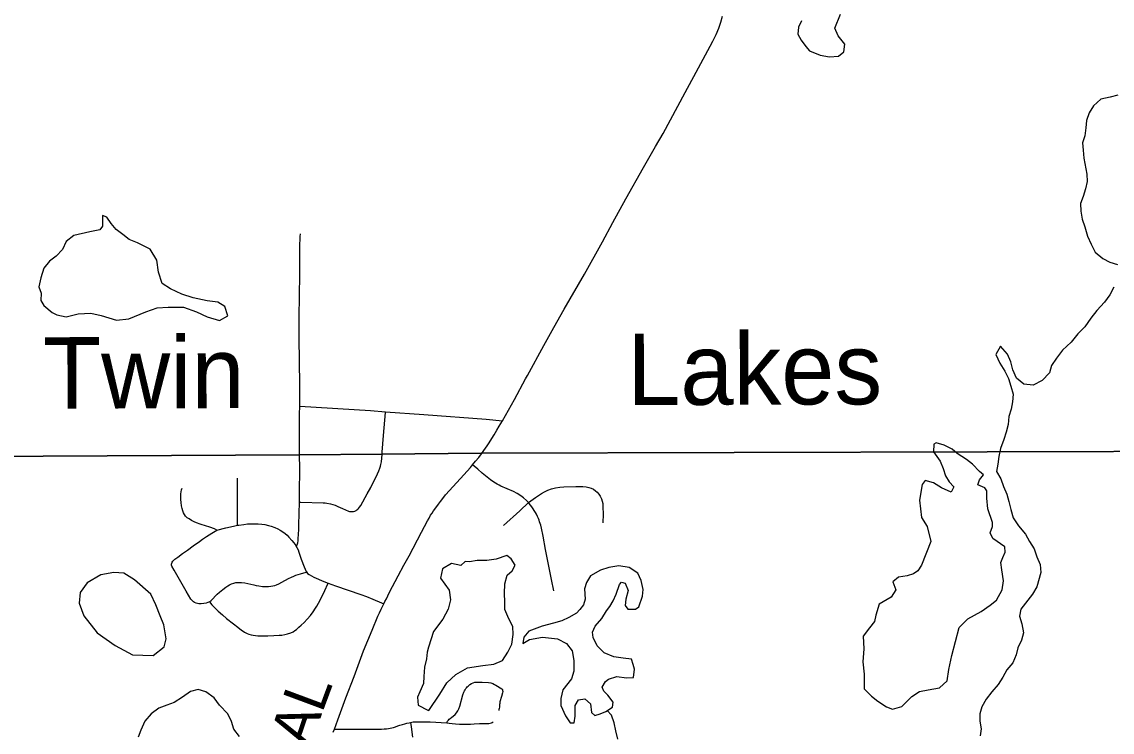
# Model space of a CAD drawing. Extents: x 0 to 34, y 0 to 22.
# Drawn here: x 3.103 to 4.548, y 17.124 to 18.065 of the extents above; entities that cross this region are included whole.
import ezdxf

# ---------------------------------------------------------------- set-up
doc = ezdxf.new("R2010")
doc.units = 0
for name, color, linetype in [('GM_X_City_Street', 7, 'Continuous'), ('GM_X_Corporation', 7, 'Continuous'), ('GM_X_County_Road', 7, 'Continuous'), ('GM_X_County_Road_Text', 7, 'Continuous'), ('GM_X_Major_Lake', 7, 'Continuous'), ('GM_X_Minor_Lake', 7, 'Continuous'), ('GM_X_Minor_Lake_Text', 7, 'Continuous'), ('GM_X_Minor_River', 7, 'Continuous'), ('GM_X_Township_Road', 7, 'Continuous')]:
    doc.layers.add(name, color=color, linetype=linetype)

msp = doc.modelspace()

# ---------------------------------------------------------------- linework, layer by layer
at = {"layer": 'GM_X_City_Street'}
for points in [[(3.4712, 17.556), (3.4711, 17.5721), (3.4711, 17.5882), (3.4709, 17.6117), (3.4705, 17.6502), (3.4703, 17.6723), (3.4707, 17.7039), (3.4712, 17.7287), (3.4712, 17.7673), (3.4714, 17.7711), (3.4716, 17.7764), (3.4719, 17.7806), (3.4724, 17.7843)], [(3.4712, 17.556), (3.5651, 17.5501), (3.5849, 17.5486), (3.6358, 17.5448), (3.7183, 17.5386), (3.7401, 17.5366)]]:
    msp.add_lwpolyline(points, dxfattribs=at)
at = {"layer": 'GM_X_Corporation'}
for points in [[(2.1, 20.9), (2.1, 17.4875), (2.1449, 17.4882), (2.5812, 17.4925), (2.6352, 17.4929), (3.0456, 17.4894), (3.4708, 17.4915), (3.5801, 17.4924), (3.7119, 17.4934), (4.718, 17.4962)], [(4.718, 17.4962), (3.7119, 17.4934), (3.5801, 17.4924), (3.4708, 17.4915), (3.0456, 17.4894), (2.6352, 17.4929), (2.5812, 17.4925), (2.1449, 17.4882), (2.1, 17.4875), (2.1, 14.1), (5.0398, 14.1)], [(3.0456, 17.4894), (3.4708, 17.4915), (3.5801, 17.4924), (3.7119, 17.4934), (4.718, 17.4962)]]:
    msp.add_lwpolyline(points, dxfattribs=at)
at = {"layer": 'GM_X_County_Road'}
for points in [[(3.7706, 17.592), (3.773, 17.5964), (3.7947, 17.6362), (3.8081, 17.66), (3.8218, 17.6844), (3.8485, 17.7307), (3.8724, 17.7735), (3.8861, 17.7992), (3.9036, 17.8307), (3.927, 17.8724), (3.9427, 17.9), (3.9528, 17.9171), (3.9629, 17.9356), (3.9822, 17.9717), (3.9967, 17.9985), (4.0152, 18.033), (4.0189, 18.0396), (4.0232, 18.0487), (4.0266, 18.0568), (4.0294, 18.0647), (4.0318, 18.0727)], [(3.7401, 17.5366), (3.7557, 17.5648), (3.7706, 17.592)], [(3.7121, 17.4928), (3.7152, 17.4971), (3.7176, 17.5003), (3.7198, 17.5034), (3.7224, 17.5074), (3.726, 17.513), (3.7289, 17.5179), (3.7325, 17.5239), (3.7356, 17.5294), (3.7401, 17.5366)], [(3.7003, 17.4781), (3.7044, 17.483), (3.7084, 17.4878), (3.7121, 17.4928)], [(3.5825, 17.2937), (3.5841, 17.297), (3.586, 17.3007), (3.588, 17.3046), (3.5904, 17.3093), (3.6016, 17.3308), (3.6093, 17.345), (3.6161, 17.3575), (3.6328, 17.3887), (3.6405, 17.4037), (3.6426, 17.4073), (3.6447, 17.4113), (3.6466, 17.4142), (3.6484, 17.4171), (3.6515, 17.4212), (3.655, 17.4262), (3.6577, 17.4295), (3.661, 17.4337), (3.6646, 17.4382), (3.6845, 17.4601), (3.6976, 17.4748), (3.7003, 17.4781)], [(3.5172, 17.1279), (3.5216, 17.1401), (3.5324, 17.1693), (3.5434, 17.1977), (3.5559, 17.2315), (3.567, 17.2591), (3.5747, 17.2774), (3.5768, 17.2818), (3.5792, 17.2869), (3.5818, 17.2923), (3.5825, 17.2937)], [(3.5157, 17.1237), (3.5172, 17.1279)]]:
    msp.add_lwpolyline(points, dxfattribs=at)
at = {"layer": 'GM_X_Major_Lake'}
for points in [[(4.5556, 17.9683), (4.5455, 17.9655), (4.5334, 17.9628), (4.5236, 17.954), (4.5176, 17.9445), (4.5143, 17.9346), (4.5132, 17.9247), (4.5122, 17.9144), (4.5088, 17.9049), (4.5097, 17.8951), (4.5105, 17.8845), (4.5145, 17.8633), (4.5149, 17.8538), (4.5131, 17.8439), (4.5098, 17.834), (4.5064, 17.8245), (4.5065, 17.8143), (4.5085, 17.8037), (4.512, 17.7935), (4.5155, 17.7814), (4.5205, 17.7708), (4.5259, 17.7602), (4.5358, 17.7516), (4.5453, 17.7467), (4.5551, 17.7437)], [(4.5504, 17.7134), (4.5452, 17.7035), (4.5381, 17.6939), (4.528, 17.6828), (4.5201, 17.6725), (4.5119, 17.6611), (4.5029, 17.6516), (4.4939, 17.6409), (4.4822, 17.6302), (4.4743, 17.6195), (4.468, 17.6099), (4.465, 17.6001), (4.4553, 17.5901), (4.4436, 17.5836), (4.4311, 17.585), (4.4216, 17.5929), (4.4166, 17.6042), (4.4138, 17.6148), (4.4096, 17.6247), (4.4, 17.6352), (4.3941, 17.6245), (4.3991, 17.6128), (4.406, 17.6023), (4.4106, 17.5924), (4.4137, 17.5826), (4.4168, 17.5716), (4.4161, 17.5618), (4.4143, 17.5519), (4.4114, 17.542), (4.4103, 17.5318), (4.4077, 17.5215), (4.4044, 17.5116), (4.4003, 17.4998), (4.3978, 17.4892), (4.3967, 17.4789), (4.3949, 17.4694), (4.4007, 17.4596), (4.4041, 17.4494), (4.4084, 17.4392), (4.4111, 17.4294), (4.4138, 17.4188), (4.417, 17.4078), (4.4242, 17.3972), (4.4334, 17.3863), (4.4388, 17.3765), (4.4449, 17.3667), (4.4484, 17.3561), (4.4526, 17.3459), (4.4535, 17.3356), (4.4483, 17.3166), (4.4427, 17.3067), (4.427, 17.2869), (4.4255, 17.2774), (4.4283, 17.2672), (4.4306, 17.2555), (4.4281, 17.2456), (4.4232, 17.2357), (4.421, 17.2262), (4.4166, 17.2159), (4.4087, 17.2064), (4.4035, 17.1968), (4.3971, 17.1869), (4.3885, 17.1774), (4.3814, 17.1675), (4.3754, 17.1576), (4.3728, 17.1481), (4.3729, 17.1386), (4.3745, 17.1284), (4.3734, 17.1189)]]:
    msp.add_lwpolyline(points, dxfattribs=at)
at = {"layer": 'GM_X_Minor_Lake'}
for p, q in [((4.1358, 18.0412), (4.1423, 18.0326)), ((3.1282, 17.7057), (3.1279, 17.6959)), ((4.3078, 17.3766), (4.2956, 17.345)), ((3.2736, 17.3068), (3.2523, 17.3256)), ((3.8485, 17.3139), (3.8497, 17.3002)), ((3.6487, 17.2573), (3.6421, 17.2364))]:
    msp.add_line(p, q, dxfattribs=at)
for points in [[(4.1423, 18.0326), (4.1472, 18.0269), (4.1613, 18.0209), (4.1734, 18.0188), (4.1855, 18.0196), (4.1923, 18.0257), (4.1937, 18.0356), (4.1849, 18.0469), (4.1807, 18.0571), (4.1881, 18.0754)], [(4.1363, 18.0666), (4.1322, 18.0583), (4.1315, 18.0488), (4.1358, 18.0412)], [(3.1279, 17.6959), (3.1318, 17.6891), (3.1428, 17.68), (3.1493, 17.6771), (3.1614, 17.6745), (3.1776, 17.6784), (3.1943, 17.6793), (3.2079, 17.676), (3.2284, 17.6701), (3.2447, 17.6717), (3.2673, 17.681), (3.2824, 17.6861), (3.2968, 17.6873), (3.3172, 17.6871), (3.3343, 17.6808), (3.3484, 17.6741), (3.3647, 17.6693), (3.376, 17.6758), (3.3721, 17.6879), (3.3626, 17.6939), (3.3486, 17.6953), (3.33, 17.6997), (3.3148, 17.7045), (3.3, 17.7112), (3.289, 17.7183), (3.2839, 17.7335), (3.2819, 17.7494), (3.2731, 17.7641), (3.256, 17.7723), (3.245, 17.7768), (3.2366, 17.7836), (3.2279, 17.7899), (3.221, 17.7982), (3.2156, 17.8065), (3.2095, 17.8088), (3.2097, 17.7943), (3.2063, 17.7894), (3.1931, 17.787), (3.1715, 17.7823), (3.1617, 17.7742), (3.1565, 17.7636), (3.1483, 17.7548), (3.1396, 17.7479), (3.1321, 17.7388), (3.1281, 17.7258), (3.1255, 17.714), (3.1282, 17.7057)], [(4.2956, 17.345), (4.2907, 17.3378), (4.2847, 17.3336), (4.2764, 17.3312), (4.265, 17.3293), (4.2575, 17.3231), (4.2614, 17.3125), (4.2554, 17.3026), (4.2392, 17.2934), (4.2348, 17.279), (4.2333, 17.2706), (4.2266, 17.2622), (4.218, 17.2511), (4.2189, 17.2341), (4.2179, 17.217), (4.2195, 17.2007), (4.2193, 17.1814), (4.2292, 17.1716), (4.2376, 17.1648), (4.249, 17.1573), (4.257, 17.1544), (4.2694, 17.1579), (4.2826, 17.1709), (4.2927, 17.1778), (4.3044, 17.1801), (4.3192, 17.1825), (4.3297, 17.1917), (4.3319, 17.2069), (4.3359, 17.2255), (4.3454, 17.2624), (4.3567, 17.2742), (4.3744, 17.2838), (4.3864, 17.2923), (4.3947, 17.2988), (4.4026, 17.3125), (4.404, 17.3246), (4.402, 17.339), (4.4008, 17.3489), (4.4034, 17.3554), (4.4063, 17.3626), (4.4059, 17.3694), (4.3899, 17.3807), (4.3865, 17.3878), (4.3894, 17.3962), (4.3894, 17.4019), (4.3836, 17.4197), (4.3823, 17.4341), (4.3822, 17.4436), (4.3796, 17.4477), (4.3701, 17.4518), (4.3723, 17.4583), (4.3775, 17.4648), (4.3722, 17.4693), (4.363, 17.4791), (4.355, 17.4851), (4.3429, 17.4933), (4.336, 17.4989), (4.3254, 17.5042), (4.3151, 17.5071), (4.3117, 17.5056), (4.3114, 17.4953), (4.3202, 17.4829), (4.3241, 17.4731), (4.3272, 17.4636), (4.3322, 17.4557), (4.3383, 17.4489), (4.3346, 17.4417), (4.322, 17.4476), (4.3114, 17.4544), (4.3004, 17.4573), (4.2963, 17.452), (4.2926, 17.4315), (4.2955, 17.4084), (4.3031, 17.3963), (4.3078, 17.3766)], [(3.6421, 17.2364), (3.6402, 17.23), (3.6391, 17.2212), (3.6366, 17.2098), (3.6355, 17.1977), (3.6352, 17.1882), (3.6304, 17.1772), (3.6274, 17.17), (3.6283, 17.1597), (3.6408, 17.153), (3.6423, 17.1526), (3.6569, 17.174), (3.6663, 17.1892), (3.6783, 17.2003), (3.6934, 17.2092), (3.7138, 17.212), (3.7285, 17.214), (3.7402, 17.2186), (3.7469, 17.2297), (3.7522, 17.2403), (3.7543, 17.2532), (3.7535, 17.2638), (3.7485, 17.274), (3.7431, 17.2865), (3.743, 17.2964), (3.7426, 17.3078), (3.7432, 17.3203), (3.7461, 17.3317), (3.7529, 17.3378), (3.7566, 17.345), (3.7517, 17.3537), (3.7456, 17.3578), (3.7316, 17.3532), (3.7191, 17.3512), (3.7066, 17.3515), (3.6964, 17.3495), (3.6907, 17.3502), (3.6847, 17.3445), (3.6726, 17.3474), (3.6605, 17.3401), (3.658, 17.328), (3.6691, 17.3121), (3.6711, 17.2992), (3.6678, 17.2867), (3.6607, 17.2737), (3.6487, 17.2573)], [(3.2523, 17.3256), (3.2378, 17.3345), (3.2246, 17.3356), (3.2076, 17.3324), (3.1895, 17.3217), (3.1801, 17.3091), (3.1787, 17.295), (3.1849, 17.278), (3.2025, 17.2554), (3.2265, 17.2385), (3.2493, 17.2262), (3.2769, 17.2256), (3.2916, 17.2371), (3.2941, 17.2474), (3.291, 17.2659), (3.2863, 17.278), (3.2802, 17.2924), (3.2736, 17.3068)], [(3.8497, 17.3002), (3.8475, 17.2926), (3.8423, 17.2862), (3.8381, 17.2816), (3.828, 17.2758), (3.8185, 17.2712), (3.8076, 17.2681), (3.7925, 17.2641), (3.7751, 17.2579), (3.7684, 17.2499), (3.7669, 17.2412), (3.776, 17.2466), (3.793, 17.2497), (3.813, 17.2476), (3.8248, 17.2413), (3.8325, 17.2315), (3.8345, 17.2186), (3.8346, 17.2046), (3.8316, 17.1943), (3.82, 17.1798), (3.8174, 17.1684), (3.8175, 17.1593), (3.8233, 17.1453), (3.8298, 17.1363), (3.8351, 17.1363), (3.8362, 17.145), (3.8364, 17.1591), (3.8409, 17.1667), (3.8492, 17.1679), (3.8565, 17.1615), (3.8581, 17.1498), (3.8623, 17.146), (3.8694, 17.1483), (3.877, 17.1514), (3.8857, 17.1568), (3.8867, 17.1636), (3.8795, 17.1727), (3.8745, 17.1783), (3.8722, 17.1836), (3.8767, 17.1909), (3.8804, 17.1939), (3.8914, 17.1978), (3.9043, 17.196), (3.9137, 17.1961), (3.9148, 17.2071), (3.9132, 17.2135), (3.9109, 17.2207), (3.8999, 17.2218), (3.8874, 17.2236), (3.8749, 17.2288), (3.8657, 17.2382), (3.86, 17.2491), (3.8595, 17.2563), (3.8629, 17.2643), (3.8719, 17.2746), (3.8778, 17.2845), (3.8823, 17.2903), (3.8868, 17.2979), (3.8905, 17.3066), (3.895, 17.3196), (3.8976, 17.3226), (3.9025, 17.3211), (3.9064, 17.3117), (3.9035, 17.3003), (3.9024, 17.2919), (3.9062, 17.287), (3.9164, 17.2867), (3.9209, 17.2898), (3.9254, 17.3039), (3.9264, 17.313), (3.9237, 17.3247), (3.9195, 17.3345), (3.9077, 17.342), (3.8944, 17.3442), (3.8808, 17.3422), (3.8699, 17.3387), (3.8567, 17.331), (3.8514, 17.3222), (3.8485, 17.3139)], [(3.3913, 17.1181), (3.3836, 17.1279), (3.3809, 17.1381), (3.3759, 17.1483), (3.3649, 17.1596), (3.3576, 17.1694), (3.3469, 17.1773), (3.3367, 17.1802), (3.3265, 17.1779), (3.3159, 17.1702), (3.3046, 17.1633), (3.2948, 17.1598), (3.2843, 17.1555), (3.2741, 17.1483), (3.2659, 17.1383), (3.2606, 17.1265), (3.2569, 17.117)]]:
    msp.add_lwpolyline(points, dxfattribs=at)
at = {"layer": 'GM_X_Minor_River'}
msp.add_lwpolyline([(3.8928, 17.1144), (3.8901, 17.1254), (3.8881, 17.136), (3.8846, 17.1465), (3.8786, 17.1524)], dxfattribs=at)
at = {"layer": 'GM_X_Township_Road'}
for points in [[(3.471, 17.4909), (3.471, 17.5036), (3.471, 17.5454), (3.4712, 17.556)], [(3.5803, 17.4919), (3.5806, 17.4951), (3.5823, 17.5172), (3.5848, 17.5473), (3.5849, 17.5486)], [(3.4707, 17.4286), (3.4725, 17.4286), (3.5021, 17.4278), (3.5047, 17.4276), (3.5072, 17.4273), (3.5118, 17.4265), (3.5151, 17.4256), (3.5181, 17.4246), (3.5216, 17.4231), (3.5277, 17.4203), (3.5358, 17.4168), (3.5372, 17.4164), (3.5388, 17.4161), (3.5406, 17.4161), (3.5424, 17.4163), (3.5443, 17.4169), (3.5458, 17.4175), (3.5471, 17.4185), (3.5482, 17.4194), (3.5491, 17.4204), (3.5506, 17.4222), (3.5521, 17.4244), (3.5608, 17.4395), (3.5656, 17.4482), (3.5743, 17.466), (3.5762, 17.4701), (3.5774, 17.4735), (3.5782, 17.4762), (3.5788, 17.4787), (3.5794, 17.4823), (3.5803, 17.4919)], [(3.4707, 17.4286), (3.4708, 17.4401), (3.4711, 17.4737), (3.471, 17.4909)], [(3.7745, 17.428), (3.7735, 17.429), (3.7716, 17.431), (3.7678, 17.4343), (3.7643, 17.437), (3.7595, 17.44), (3.7545, 17.4426), (3.738, 17.45), (3.7354, 17.4512), (3.733, 17.4524), (3.7309, 17.4537), (3.7283, 17.4553), (3.7243, 17.4581), (3.7132, 17.467), (3.7071, 17.4723), (3.7003, 17.4781)], [(3.3888, 17.398), (3.3888, 17.3995), (3.3888, 17.4149), (3.3887, 17.4346), (3.3886, 17.4527), (3.3887, 17.4606)], [(3.7745, 17.428), (3.7836, 17.4349), (3.7917, 17.4403), (3.7955, 17.4425), (3.8001, 17.4446), (3.8048, 17.4463), (3.8103, 17.4477), (3.8158, 17.4487), (3.8215, 17.4492), (3.837, 17.4495), (3.8464, 17.4495), (3.8508, 17.4491), (3.8546, 17.4482), (3.8576, 17.4471), (3.8605, 17.4457), (3.8631, 17.4438), (3.8655, 17.4417), (3.8676, 17.4392), (3.8694, 17.4366), (3.8712, 17.4332), (3.8723, 17.4301), (3.8729, 17.427), (3.8732, 17.4225), (3.8734, 17.4126), (3.873, 17.4013)], [(3.3614, 17.3917), (3.3582, 17.3933), (3.3521, 17.3954), (3.3461, 17.3974), (3.3405, 17.3991), (3.3379, 17.4), (3.3355, 17.4008), (3.332, 17.4022), (3.3276, 17.4045), (3.3244, 17.4065), (3.3219, 17.4081), (3.3197, 17.4103), (3.3183, 17.4122), (3.317, 17.4147), (3.3161, 17.4171), (3.3152, 17.4202), (3.3143, 17.4236), (3.3138, 17.428), (3.3135, 17.4323), (3.3136, 17.4396), (3.3139, 17.4423), (3.3146, 17.4448), (3.3155, 17.4471)], [(3.4666, 17.37), (3.4677, 17.372), (3.4685, 17.3748), (3.4689, 17.3775), (3.4692, 17.3802), (3.4698, 17.3924), (3.4702, 17.3985), (3.4707, 17.4286)], [(3.7412, 17.3979), (3.763, 17.4173), (3.7745, 17.428)], [(3.8081, 17.311), (3.805, 17.3263), (3.8003, 17.3503), (3.797, 17.3661), (3.7937, 17.3838), (3.7918, 17.3944), (3.7909, 17.3981), (3.7901, 17.4005), (3.7892, 17.4028), (3.7884, 17.405), (3.7876, 17.4071), (3.7864, 17.4097), (3.7849, 17.4128), (3.7837, 17.4151), (3.7821, 17.4177), (3.7806, 17.42), (3.779, 17.4224), (3.7773, 17.4246), (3.7755, 17.4269), (3.7745, 17.428)], [(3.3021, 17.3491), (3.3031, 17.3505), (3.304, 17.3515), (3.3056, 17.3529), (3.3094, 17.3558), (3.3157, 17.3606), (3.3223, 17.3651), (3.33, 17.3707), (3.3382, 17.3766), (3.3422, 17.3795), (3.3477, 17.3832), (3.3548, 17.3876), (3.3614, 17.3917)], [(3.3614, 17.3917), (3.373, 17.3947), (3.3833, 17.397), (3.3888, 17.398)], [(3.3888, 17.398), (3.3906, 17.3983), (3.3969, 17.3992), (3.4018, 17.3998), (3.4063, 17.4), (3.4112, 17.4001), (3.4161, 17.3998), (3.421, 17.3995), (3.4249, 17.3989), (3.4298, 17.3978), (3.4335, 17.3967), (3.4381, 17.3951), (3.442, 17.3933), (3.4451, 17.3916), (3.4488, 17.3894), (3.4518, 17.3872), (3.4547, 17.3849), (3.4569, 17.3823), (3.4607, 17.378), (3.4634, 17.3746), (3.466, 17.3711), (3.4666, 17.37)], [(3.4666, 17.37), (3.4673, 17.3687), (3.4689, 17.3653), (3.4699, 17.3625), (3.4732, 17.3529), (3.477, 17.3429), (3.4782, 17.3397), (3.4797, 17.3369), (3.4802, 17.3361)], [(3.3515, 17.2964), (3.3494, 17.2955), (3.347, 17.2948), (3.3442, 17.2942), (3.3407, 17.2939), (3.3376, 17.294), (3.3355, 17.2943), (3.3337, 17.2948), (3.3318, 17.2955), (3.3305, 17.2964), (3.3293, 17.2974), (3.3281, 17.2987), (3.3269, 17.3003), (3.3205, 17.3107), (3.3081, 17.3322), (3.3045, 17.3386), (3.3017, 17.344), (3.3014, 17.3453), (3.3014, 17.3466), (3.3016, 17.3479), (3.3021, 17.3491)], [(3.3515, 17.2964), (3.3538, 17.2985), (3.3619, 17.3067), (3.365, 17.3095), (3.3691, 17.3129), (3.3733, 17.316), (3.3757, 17.3176), (3.3782, 17.3189), (3.3808, 17.3203), (3.3838, 17.3214), (3.3866, 17.3221), (3.3895, 17.3224), (3.3918, 17.3223), (3.394, 17.3222), (3.3983, 17.3216), (3.4104, 17.3191), (3.4133, 17.3183), (3.4169, 17.3177), (3.4217, 17.3171), (3.4254, 17.3168), (3.4276, 17.3167), (3.4298, 17.3168), (3.433, 17.3172), (3.4357, 17.3177), (3.438, 17.3183), (3.4404, 17.3191), (3.4436, 17.3206), (3.4475, 17.3225), (3.4563, 17.3273), (3.4602, 17.3293), (3.4635, 17.3307), (3.4662, 17.3317), (3.4689, 17.3327), (3.4722, 17.3338), (3.4795, 17.3359), (3.4802, 17.3361)], [(3.4802, 17.3361), (3.4817, 17.3343), (3.4835, 17.3329), (3.4866, 17.331), (3.4899, 17.3292), (3.5031, 17.3236), (3.509, 17.3214)], [(3.3515, 17.2964), (3.3545, 17.2927), (3.358, 17.2889), (3.3631, 17.2844), (3.3688, 17.2794), (3.3743, 17.2746), (3.3833, 17.2675), (3.389, 17.2629), (3.3941, 17.259), (3.3961, 17.2575), (3.3978, 17.2564), (3.3996, 17.2553), (3.4016, 17.2546), (3.4039, 17.2537), (3.4068, 17.2529), (3.4096, 17.2524), (3.4125, 17.2521), (3.4156, 17.2517), (3.4226, 17.2514), (3.4287, 17.2513), (3.437, 17.2518), (3.444, 17.2522), (3.4476, 17.2525), (3.4514, 17.2531), (3.455, 17.254), (3.4592, 17.2554), (3.4624, 17.257), (3.4649, 17.2585), (3.467, 17.2601), (3.4701, 17.2628), (3.4733, 17.2656), (3.4769, 17.2691), (3.4812, 17.2737), (3.4853, 17.2785), (3.4888, 17.2831), (3.492, 17.2881), (3.4937, 17.2908), (3.496, 17.2947), (3.4995, 17.3016), (3.5044, 17.3115), (3.5085, 17.3204), (3.509, 17.3214)], [(3.509, 17.3214), (3.5188, 17.3178), (3.5523, 17.3063), (3.5599, 17.3035), (3.5679, 17.3003), (3.5795, 17.2951), (3.5825, 17.2937)], [(3.6662, 17.136), (3.6673, 17.1382), (3.6685, 17.1399), (3.6695, 17.141), (3.6707, 17.1421), (3.6729, 17.1438), (3.6748, 17.1451), (3.6771, 17.1471), (3.6791, 17.1494), (3.6808, 17.1521), (3.6822, 17.1548), (3.6833, 17.1583), (3.6874, 17.1733), (3.6888, 17.1768), (3.6896, 17.1784), (3.6905, 17.1801), (3.6915, 17.1816), (3.6923, 17.1827), (3.6932, 17.1837), (3.6943, 17.185), (3.6967, 17.187), (3.6988, 17.1883), (3.7011, 17.1893), (3.7035, 17.1899), (3.7078, 17.1903), (3.7132, 17.1903), (3.7214, 17.1897), (3.7244, 17.1891), (3.7273, 17.1881), (3.7293, 17.187), (3.7312, 17.1861), (3.7391, 17.1811), (3.7399, 17.1802), (3.7402, 17.179), (3.7403, 17.1778), (3.7399, 17.1759), (3.7386, 17.1712), (3.7366, 17.164), (3.7364, 17.162), (3.7362, 17.1605), (3.736, 17.1587), (3.7358, 17.1568), (3.7355, 17.1554), (3.7352, 17.1539), (3.735, 17.1527)], [(3.5172, 17.1279), (3.5233, 17.1279), (3.546, 17.1277), (3.564, 17.1277), (3.5794, 17.1278), (3.583, 17.1281), (3.5862, 17.1283), (3.589, 17.1287), (3.591, 17.1289), (3.5934, 17.1294), (3.5957, 17.1301), (3.5983, 17.131), (3.6012, 17.132), (3.6039, 17.1329), (3.6074, 17.1341), (3.6104, 17.1349), (3.6133, 17.1357), (3.6161, 17.1363), (3.6181, 17.1368), (3.6216, 17.1373), (3.6231, 17.1375), (3.6258, 17.1376), (3.628, 17.1377), (3.6442, 17.1374), (3.6662, 17.136), (3.6694, 17.1356), (3.6732, 17.1351), (3.6779, 17.1348), (3.6828, 17.1344), (3.6876, 17.1344), (3.6921, 17.1343), (3.6974, 17.1346), (3.7026, 17.1348), (3.7094, 17.1352), (3.7148, 17.1352), (3.7193, 17.1352), (3.7217, 17.1355), (3.7235, 17.1357), (3.7253, 17.1361), (3.7264, 17.1367), (3.7275, 17.1374)], [(3.6181, 17.1368), (3.619, 17.1308), (3.6208, 17.1172)]]:
    msp.add_lwpolyline(points, dxfattribs=at)

# ---------------------------------------------------------------- texts
at = {"layer": 'GM_X_County_Road_Text'}
for s, rotation, p in [('L', 69.6173, (3.5007, 17.148)), ('A', 71.1095, (3.4846, 17.101))]:
    msp.add_text(s, height=0.0568, rotation=rotation, dxfattribs=at).set_placement(p)
at = {"layer": 'GM_X_Minor_Lake_Text'}
for s, rotation, p in [('Twin', 0.1732, (3.1307, 17.5525)), ('Lakes', 0.1742, (3.9054, 17.5574))]:
    msp.add_text(s, height=0.09474, rotation=rotation, dxfattribs=at).set_placement(p)

doc.saveas('drawing.dxf')
